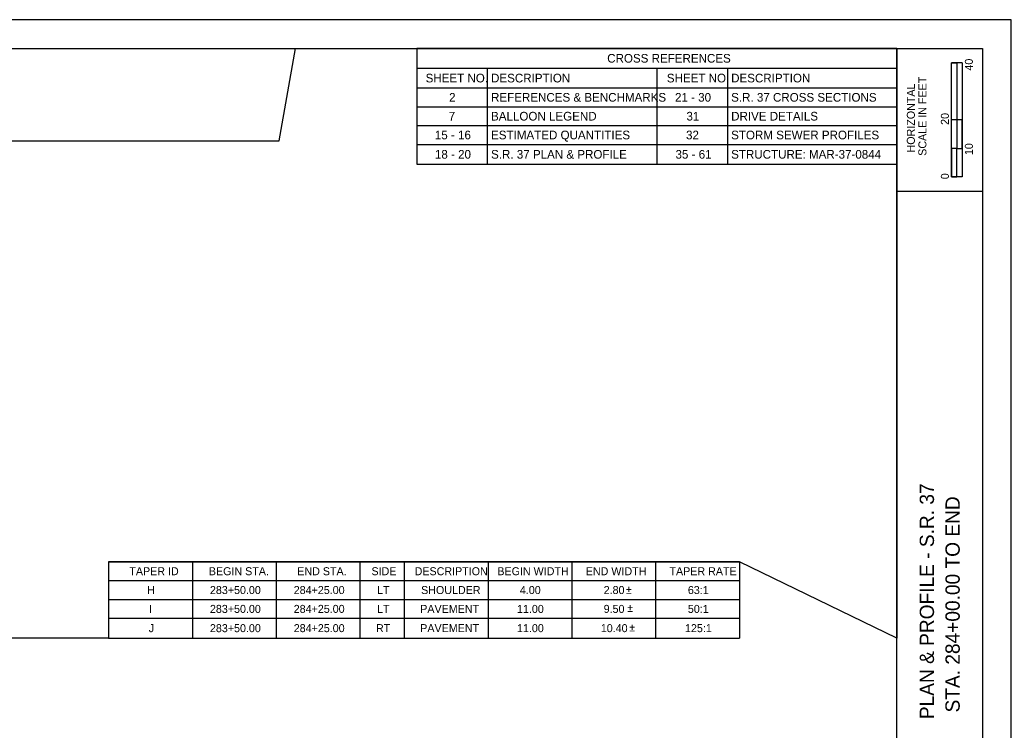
# Model space of a CAD drawing. Extents: x -0.7 to 34, y 0 to 22.
# Drawn here: x 16.66 to 34, y 9.57 to 22 of the extents above; entities that cross this region are included whole.
import ezdxf

# ---------------------------------------------------------------- set-up
doc = ezdxf.new("R2010")
doc.units = 0
for name, color, linetype in [('RW_X_CL', 7, 'Continuous'), ('RW_X_CL_100_Bearings', 7, 'Continuous'), ('RW_X_Esmt_SH', 7, 'Continuous'), ('RW_X_Fee_RW', 7, 'Continuous'), ('SC_Scratch1', 7, 'Continuous')]:
    doc.layers.add(name, color=color, linetype=linetype)

msp = doc.modelspace()

# ---------------------------------------------------------------- linework, layer by layer
at = {"layer": 'RW_X_CL'}
for p, q in [((23.6, 21.5), (32, 21.5)), ((32, 21.5), (32, 19.474)), ((32.957, 19.25), (32.957, 21.25)), ((33.144, 21.25), (32.957, 21.25)), ((32.957, 20.25), (32.957, 21.25)), ((32.957, 21.25), (33.05, 21.25)), ((33.05, 21.25), (33.051, 21.25)), ((33.051, 21.25), (33.051, 20.25)), ((33.144, 21.25), (33.144, 19.25)), ((33.051, 20.25), (32.957, 20.25)), ((33.143, 20.25), (33.05, 20.25)), ((33.05, 20.25), (33.05, 19.75)), ((33.143, 19.75), (33.143, 20.25)), ((33.05, 19.75), (32.957, 19.75)), ((32.957, 19.75), (32.957, 19.25)), ((33.05, 19.25), (33.05, 19.75)), ((33.05, 19.75), (33.143, 19.75)), ((33.144, 19.25), (32.957, 19.25)), ((32.957, 19.25), (33.05, 19.25)), ((18.21, 12.517), (29.246, 12.517)), ((18.21, 12.517), (18.21, 11.183)), ((19.676, 12.517), (19.676, 11.183)), ((21.142, 12.517), (21.142, 11.183)), ((22.608, 12.517), (22.608, 11.183)), ((23.382, 12.517), (23.382, 11.183)), ((24.848, 12.517), (24.848, 11.183)), ((26.314, 12.517), (26.314, 11.183)), ((27.78, 12.517), (27.78, 11.183)), ((29.246, 12.517), (29.246, 11.183)), ((18.21, 12.187), (29.246, 12.187)), ((18.21, 11.858), (29.246, 11.858)), ((18.21, 11.529), (29.246, 11.529)), ((18.21, 11.183), (29.246, 11.183))]:
    msp.add_line(p, q, dxfattribs=at)
at = {"layer": 'RW_X_Esmt_SH'}
msp.add_lwpolyline([(0, 0), (34, 0), (34, 22), (0, 22)], close=True, dxfattribs=at)
at = {"layer": 'RW_X_Fee_RW'}
for points in [[(4.206, 20.199), (5.473, 20.736), (7.762, 21.5), (9.488, 21.5), (9.492, 19.88), (21.195, 19.88), (21.48, 21.5), (23.6, 21.5), (23.6, 19.474), (32, 19.474), (32, 11.183), (29.246, 12.517), (18.21, 12.517), (18.21, 11.183), (4.298, 11.183), (4.282, 12.75), (4.074, 13.621), (3.93, 17.752), (4.218, 18.75)], [(23.6, 19.474), (32, 19.474), (32, 21.5), (23.6, 21.5)]]:
    msp.add_lwpolyline(points, close=True, dxfattribs=at)
at = {"layer": 'SC_Scratch1'}
for p, q in [((23.6, 21.5), (32, 21.5)), ((23.6, 21.5), (23.6, 19.474)), ((32, 0.5), (32, 21.5)), ((32, 21.5), (32, 19.474)), ((23.6, 21.154), (32, 21.154)), ((24.835, 21.154), (24.835, 19.474)), ((27.8, 21.154), (27.8, 19.474)), ((29.035, 21.154), (29.035, 19.474)), ((23.6, 20.808), (32, 20.808)), ((23.6, 20.479), (32, 20.479)), ((23.6, 20.149), (32, 20.149)), ((23.6, 19.82), (32, 19.82)), ((23.6, 19.474), (32, 19.474)), ((32, 19), (33.5, 19))]:
    msp.add_line(p, q, dxfattribs=at)
msp.add_lwpolyline([(1.5, 21.5), (33.5, 21.5), (33.5, 0.5), (1.5, 0.5)], close=True, dxfattribs=at)

# ---------------------------------------------------------------- texts
at = {"layer": 'RW_X_CL'}
for s, height, p in [('40', 0.14, (33.33, 21.112)), ('SCALE IN FEET', 0.14, (32.517, 19.621)), ('HORIZONTAL', 0.14, (32.315, 19.679)), ('20', 0.14, (32.91, 20.162)), ('10', 0.14, (33.33, 19.633)), ('0', 0.14, (32.91, 19.211)), ('PLAN & PROFILE - S.R. 37', 0.25, (32.65, 9.764)), ('STA. 284+00.00 TO END', 0.25, (33.1, 9.881))]:
    msp.add_text(s, height=height, rotation=90, dxfattribs=at).set_placement(p)
for p in [(27.259, 11.958), (27.283, 11.64), (27.319, 11.298)]:
    msp.add_text('±', height=0.14, dxfattribs=at).set_placement(p)
at = {"layer": 'RW_X_CL_100_Bearings'}
for s, p in [('TAPER ID', (18.573, 12.282)), ('BEGIN STA.', (19.964, 12.282)), ('END STA.', (21.511, 12.282)), ('SIDE', (22.809, 12.282)), ('DESCRIPTION', (23.564, 12.282)), ('BEGIN WIDTH', (25.011, 12.282)), ('END WIDTH', (26.558, 12.282)), ('TAPER RATE', (28.022, 12.282)), ('H', (18.882, 11.953)), ('283+50.00', (19.983, 11.953)), ('284+25.00', (21.449, 11.953)), ('LT', (22.906, 11.953)), ('SHOULDER', (23.677, 11.953)), ('4.00', (25.405, 11.953)), ('2.80', (26.871, 11.953)), ('63:1', (28.344, 11.953)), ('I', (18.919, 11.623)), ('283+50.00', (19.983, 11.623)), ('284+25.00', (21.449, 11.623)), ('LT', (22.906, 11.623)), ('PAVEMENT', (23.662, 11.623)), ('11.00', (25.355, 11.623)), ('9.50', (26.871, 11.623)), ('50:1', (28.344, 11.623)), ('J', (18.912, 11.286)), ('283+50.00', (19.983, 11.286)), ('284+25.00', (21.449, 11.286)), ('RT', (22.888, 11.286)), ('PAVEMENT', (23.662, 11.286)), ('11.00', (25.355, 11.286)), ('10.40', (26.821, 11.286)), ('125:1', (28.294, 11.286))]:
    msp.add_text(s, height=0.14, dxfattribs=at).set_placement(p)
at = {"layer": 'SC_Scratch1'}
for s, height, p in [('CROSS REFERENCES', 0.15153, (26.933, 21.251)), ('SHEET NO.', 0.1515, (23.756, 20.905)), ('DESCRIPTION', 0.15153, (24.901, 20.905)), ('SHEET NO', 0.1515, (27.976, 20.905)), ('DESCRIPTION', 0.15153, (29.101, 20.905)), ('2', 0.152, (24.167, 20.568)), ('REFERENCES & BENCHMARKS', 0.15153, (24.901, 20.568)), ('21 - 30', 0.1515, (28.119, 20.568)), ('S.R. 37 CROSS SECTIONS', 0.15153, (29.101, 20.568)), ('7', 0.152, (24.16, 20.238)), ('BALLOON LEGEND', 0.15153, (24.901, 20.238)), ('31', 0.1515, (28.319, 20.238)), ('DRIVE DETAILS', 0.15153, (29.101, 20.238)), ('15 - 16', 0.1515, (23.918, 19.909)), ('ESTIMATED QUANTITIES', 0.15153, (24.901, 19.909)), ('32', 0.1515, (28.312, 19.909)), ('STORM SEWER PROFILES', 0.15153, (29.101, 19.909)), ('18 - 20', 0.1515, (23.919, 19.571)), ('S.R. 37 PLAN & PROFILE', 0.15153, (24.901, 19.571)), ('35 - 61', 0.1515, (28.128, 19.571)), ('STRUCTURE: MAR-37-0844', 0.15153, (29.101, 19.571))]:
    msp.add_text(s, height=height, dxfattribs=at).set_placement(p)

doc.saveas('drawing.dxf')
